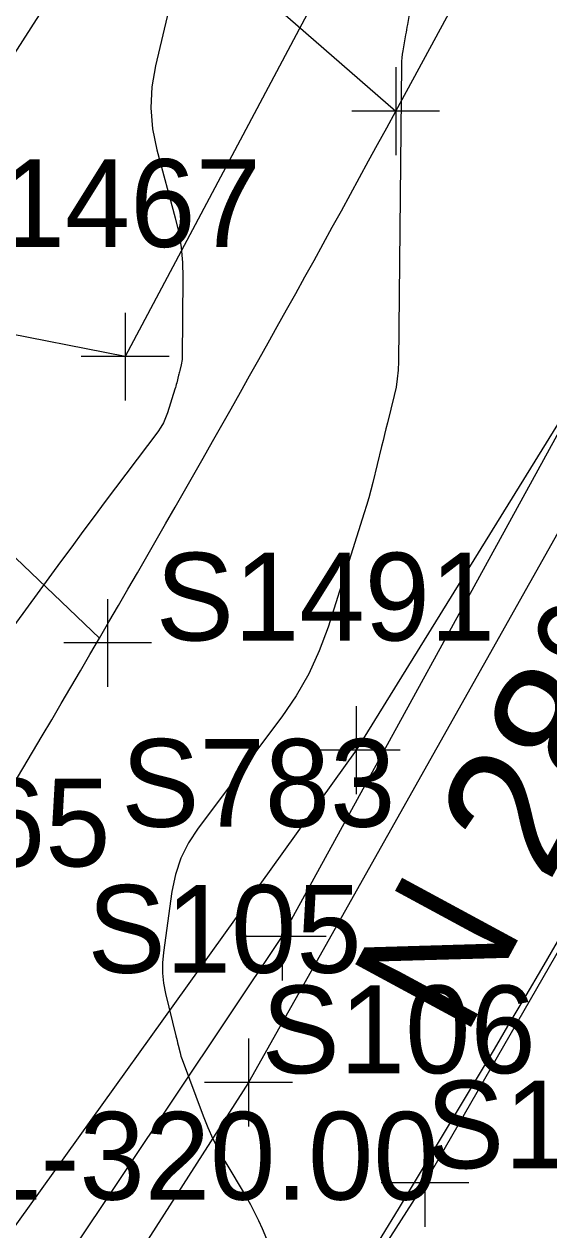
# Model space of a CAD drawing. Extents: x 816928 to 825690, y 436959 to 448212.
# Drawn here: x 819337.3 to 819361.2, y 445709.7 to 445764.7 of the extents above; entities that cross this region are included whole.
import ezdxf

# ---------------------------------------------------------------- set-up
doc = ezdxf.new("R2010")
doc.units = 0
for name, color, linetype in [('SURVEY - CENTERLINE - Preliminary', 7, 'Continuous'), ('SURVEY - CENTERLINE - Preliminary Text', 7, 'Continuous'), ('SURVEY - CONTOURS - Index with Text', 7, 'Continuous'), ('SURVEY - CONTOURS - Intermediate with optional Text', 7, 'Continuous'), ('SURVEY - DRAINAGE - Area Shapes', 7, 'Continuous'), ('SURVEY - DTM - Breaklines', 7, 'Continuous'), ('SURVEY - DTM - Breaklines - Points - Locators', 7, 'Continuous'), ('SURVEY - DTM - Breaklines - Points - Numbers', 7, 'Continuous'), ('SURVEY - NON-TRANSPORTATION - Features', 7, 'Continuous'), ('SURVEY - NON-TRANSPORTATION - Features - Points - Locators', 7, 'Continuous'), ('SURVEY - NON-TRANSPORTATION - Features - Points - Numbers', 7, 'Continuous'), ('SURVEY - PROPERTY - Parcels', 7, 'Continuous'), ('SURVEY - PROPERTY - Property Lines - Points - Elevations', 7, 'Continuous'), ('SURVEY - PROPERTY - ROW Lines', 7, 'Continuous'), ('SURVEY - PROPERTY - ROW Lines - Points - Locators', 7, 'Continuous'), ('SURVEY - PROPERTY - ROW Lines Text', 7, 'Continuous'), ('SURVEY - PROPERTY - Station and Offset Flags', 7, 'Continuous'), ('SURVEY - TRANSPORTATION - Roads', 7, 'Continuous'), ('SURVEY - TRANSPORTATION - Roads - Points - Locators', 7, 'Continuous'), ('SURVEY - TRANSPORTATION - Roads - Points - Numbers', 7, 'Continuous'), ('SURVEY - UTILITIES - Gas - Points - Locators', 7, 'Continuous'), ('SURVEY - UTILITIES - Gas - Points - Numbers', 7, 'Continuous'), ('SURVEY - UTILITIES - Gas with Text', 7, 'Continuous'), ('SURVEY - VEGETATION - Features - Points - Locators', 7, 'Continuous'), ('SURVEY - VEGETATION - Features - Points - Numbers', 7, 'Continuous'), ('SURVEY - VEGETATION - Features with Text', 7, 'Continuous')]:
    doc.layers.add(name, color=color, linetype=linetype)

msp = doc.modelspace()

# ---------------------------------------------------------------- linework, layer by layer
at = {"layer": 'SURVEY - CENTERLINE - Preliminary'}
msp.add_arc((818575.983, 446182.091), 910, 320.141729, 331.568854, dxfattribs=at)
msp.add_arc((818575.983, 446182.091), 910, 320.141729, 331.568854, dxfattribs=at)
at = {"layer": 'SURVEY - CONTOURS - Index with Text'}
msp.add_lwpolyline([(819354.877, 445765.245), (819354.778, 445764.691), (819354.757, 445764.572), (819354.736, 445764.454), (819354.715, 445764.335), (819354.694, 445764.216), (819354.565, 445763.491), (819354.54, 445763.335), (819354.522, 445763.179), (819354.511, 445763.022), (819354.506, 445762.864), (819354.371, 445749.329), (819354.356, 445748.937), (819354.318, 445748.548), (819354.258, 445748.162), (819354.175, 445747.779), (819353.867, 445746.532), (819353.801, 445746.265), (819353.735, 445745.998), (819353.669, 445745.73), (819353.603, 445745.463), (819353.198, 445743.822), (819353.108, 445743.471), (819353.013, 445743.121), (819352.912, 445742.774), (819352.805, 445742.427), (819351.16, 445737.228), (819350.763, 445736.136), (819350.28, 445735.09), (819349.709, 445734.088), (819349.051, 445733.131), (819345.24, 445728.058), (819344.803, 445727.395), (819344.459, 445726.693), (819344.208, 445725.953), (819344.051, 445725.174), (819343.667, 445722.39), (819343.624, 445721.922), (819343.625, 445721.455), (819343.671, 445720.991), (819343.761, 445720.529), (819344.232, 445718.593), (819344.258, 445718.486), (819344.284, 445718.378), (819344.31, 445718.271), (819344.336, 445718.164), (819344.422, 445717.813), (819344.441, 445717.738), (819344.463, 445717.664), (819344.486, 445717.591), (819344.512, 445717.518), (819345.47, 445714.951), (819345.684, 445714.415), (819345.921, 445713.891), (819346.181, 445713.377), (819346.465, 445712.875), (819347.429, 445711.253), (819347.629, 445710.902), (819347.817, 445710.545), (819347.992, 445710.181), (819348.154, 445709.811), (819350.257, 445704.779)], dxfattribs=at)
at = {"layer": 'SURVEY - CONTOURS - Intermediate with optional Text'}
msp.add_lwpolyline([(819347.034, 445778.626), (819343.302, 445762.814), (819343.136, 445761.854), (819343.091, 445760.896), (819343.167, 445759.94), (819343.364, 445758.986), (819344.204, 445755.872), (819344.361, 445755.202), (819344.471, 445754.526), (819344.534, 445753.843), (819344.551, 445753.155), (819344.514, 445749.505), (819344.511, 445749.424), (819344.503, 445749.343), (819344.491, 445749.262), (819344.474, 445749.182), (819344.409, 445748.923), (819344.396, 445748.867), (819344.382, 445748.811), (819344.368, 445748.756), (819344.354, 445748.7), (819344.27, 445748.358), (819344.251, 445748.285), (819344.232, 445748.212), (819344.211, 445748.14), (819344.188, 445748.068), (819343.845, 445746.984), (819343.763, 445746.757), (819343.662, 445746.539), (819343.543, 445746.33), (819343.406, 445746.131), (819341.013, 445742.945), (819340.501, 445742.262), (819339.992, 445741.577), (819339.484, 445740.89), (819338.979, 445740.202), (819334.426, 445733.977)], dxfattribs=at)
at = {"layer": 'SURVEY - DRAINAGE - Area Shapes'}
msp.add_arc((818575.983, 446182.091), 910, 320.141729, 331.568854, dxfattribs=at)
at = {"layer": 'SURVEY - DTM - Breaklines'}
msp.add_lwpolyline([(819380.404, 445755.141), (819355.578, 445711.888), (819328.616, 445669.931), (819299.268, 445629.736), (819268.215, 445590.476), (819237.204, 445551.148), (819207.272, 445511.316), (819178.097, 445471.355), (819148.961, 445430.516), (819120.831, 445389.41), (819092.595, 445348.525), (819063.764, 445307.701), (819034.576, 445266.965), (819005.716, 445226.512), (818977.706, 445187.397)], dxfattribs=at)
at = {"layer": 'SURVEY - DTM - Breaklines - Points - Locators'}
for p, q in [((819355.578, 445713.888), (819355.578, 445709.888)), ((819357.578, 445711.888), (819353.578, 445711.888))]:
    msp.add_line(p, q, dxfattribs=at)
at = {"layer": 'SURVEY - NON-TRANSPORTATION - Features'}
msp.add_lwpolyline([(819351.494, 445767.604), (819341.921, 445749.552), (819249.204, 445767.807), (819214.983, 445735.979)], dxfattribs=at)
at = {"layer": 'SURVEY - NON-TRANSPORTATION - Features - Points - Locators'}
for p, q in [((819341.921, 445751.552), (819341.921, 445747.552)), ((819343.921, 445749.552), (819339.921, 445749.552))]:
    msp.add_line(p, q, dxfattribs=at)
at = {"layer": 'SURVEY - PROPERTY - Parcels'}
msp.add_line((819354.243, 445760.74), (819359.091, 445769.695), dxfattribs=at)
msp.add_arc((818575.983, 446182.091), 885, 328.00107, 331.568854, dxfattribs=at)
at = {"layer": 'SURVEY - PROPERTY - ROW Lines'}
msp.add_line((819354.243, 445760.74), (819359.091, 445769.695), dxfattribs=at)
msp.add_arc((818575.983, 446182.091), 885, 328.00107, 331.568854, dxfattribs=at)
msp.add_arc((818575.983, 446182.091), 885, 328.00107, 331.568854, dxfattribs=at)
at = {"layer": 'SURVEY - PROPERTY - ROW Lines - Points - Locators'}
for p, q in [((819354.243, 445762.74), (819354.243, 445758.74)), ((819356.243, 445760.74), (819352.243, 445760.74)), ((819341.12, 445738.502), (819341.12, 445734.502)), ((819343.12, 445736.502), (819339.12, 445736.502))]:
    msp.add_line(p, q, dxfattribs=at)
at = {"layer": 'SURVEY - PROPERTY - ROW Lines Text'}
msp.add_lwpolyline([(819288.711, 445786.511), (819340.75, 445736.718)], dxfattribs=at)
at = {"layer": 'SURVEY - PROPERTY - Station and Offset Flags'}
msp.add_lwpolyline([(819318.164, 445792.174), (819354.243, 445760.74)], dxfattribs=at)
at = {"layer": 'SURVEY - TRANSPORTATION - Roads'}
msp.add_lwpolyline([(819372.417, 445760.729), (819347.536, 445716.465), (819327.358, 445684.931), (819320.732, 445674.576), (819313.086, 445663.907), (819291.72, 445634.092), (819261.573, 445595.794), (819230.52, 445556.026), (819202.59, 445519.473), (819200.025, 445516.115), (819183.78, 445493.817), (819171.491, 445476.948), (819142.501, 445435.003), (819121.554, 445405.003), (819114.313, 445394.631), (819108.813, 445386.861), (819085.629, 445354.103), (819056.538, 445311.65), (819028.029, 445272.038), (818998.985, 445231.035), (818970.783, 445191.785), (818984.089, 445181.723)], dxfattribs=at)
at = {"layer": 'SURVEY - TRANSPORTATION - Roads - Points - Locators'}
for p, q in [((819347.536, 445718.465), (819347.536, 445714.465)), ((819349.536, 445716.465), (819345.536, 445716.465))]:
    msp.add_line(p, q, dxfattribs=at)
at = {"layer": 'SURVEY - UTILITIES - Gas - Points - Locators'}
for p, q in [((819349.073, 445725.122), (819349.073, 445721.122)), ((819351.073, 445723.122), (819347.073, 445723.122))]:
    msp.add_line(p, q, dxfattribs=at)
at = {"layer": 'SURVEY - UTILITIES - Gas with Text'}
msp.add_lwpolyline([(818968.105, 445195.328), (818969.738, 445197.267), (819012.001, 445253.658), (819064.107, 445326.037), (819122.078, 445408.8), (819183.152, 445497.068), (819237.635, 445568.809), (819293.129, 445639.42), (819349.073, 445723.122), (819383.091, 445785.202)], dxfattribs=at)
at = {"layer": 'SURVEY - VEGETATION - Features - Points - Locators'}
for p, q in [((819352.44, 445733.613), (819352.44, 445729.613)), ((819354.44, 445731.613), (819350.44, 445731.613))]:
    msp.add_line(p, q, dxfattribs=at)
at = {"layer": 'SURVEY - VEGETATION - Features with Text'}
msp.add_line((819371.97, 445763.244), (819352.44, 445731.613), dxfattribs=at)
for points in [[(819149.151, 445746.801), (819301.413, 445718.252), (819327.818, 445749.222), (819348.831, 445782.031)], [(819352.44, 445731.613), (819311.701, 445674.795), (819246.107, 445695.818), (819141.496, 445721.023)]]:
    msp.add_lwpolyline(points, dxfattribs=at)

# ---------------------------------------------------------------- texts
at = {"layer": 'SURVEY - CENTERLINE - Preliminary Text'}
msp.add_text('N 28%%d 25\' 52" E', height=6, rotation=61.5689, dxfattribs=at).set_placement((819357.363, 445718.421))
at = {"layer": 'SURVEY - DTM - Breaklines - Points - Numbers'}
msp.add_text('S106', height=4, dxfattribs=at).set_placement((819348.132, 445716.888))
at = {"layer": 'SURVEY - NON-TRANSPORTATION - Features - Points - Numbers'}
for s, p in [('S1467', (819332.633, 445754.552)), ('S1465', (819325.785, 445726.316))]:
    msp.add_text(s, height=4, dxfattribs=at).set_placement(p)
at = {"layer": 'SURVEY - PROPERTY - Property Lines - Points - Elevations'}
msp.add_text('EL-320.00', height=4, dxfattribs=at).set_placement((819331.515, 445711.126))
at = {"layer": 'SURVEY - TRANSPORTATION - Roads - Points - Numbers'}
for s, p in [('S105', (819340.2, 445721.465)), ('S104', (819355.621, 445712.555))]:
    msp.add_text(s, height=4, dxfattribs=at).set_placement(p)
at = {"layer": 'SURVEY - UTILITIES - Gas - Points - Numbers'}
msp.add_text('S783', height=4, dxfattribs=at).set_placement((819341.737, 445728.122))
at = {"layer": 'SURVEY - VEGETATION - Features - Points - Numbers'}
msp.add_text('S1491', height=4, dxfattribs=at).set_placement((819343.31, 445736.613))

doc.saveas('drawing.dxf')
